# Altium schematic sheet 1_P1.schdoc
size 431 x 309 mm; Symbol: Sheet-Symbol_A4; Device: Sheet-Symbol_A4; Company: EasyEDA.com; Drawed: EasyEDA Pro; Reviewed: EasyEDA Pro; Version: V0.1; Page Size: A3; @Project Name: FortissKnob; @Page Count: 1; @Update Date: 2023-03-24; @Create Date: 2023-03-01; @Schematic Name: Schematic2; Part Number: JLCPCB-002; @Page No: 1; @Page Name: P1
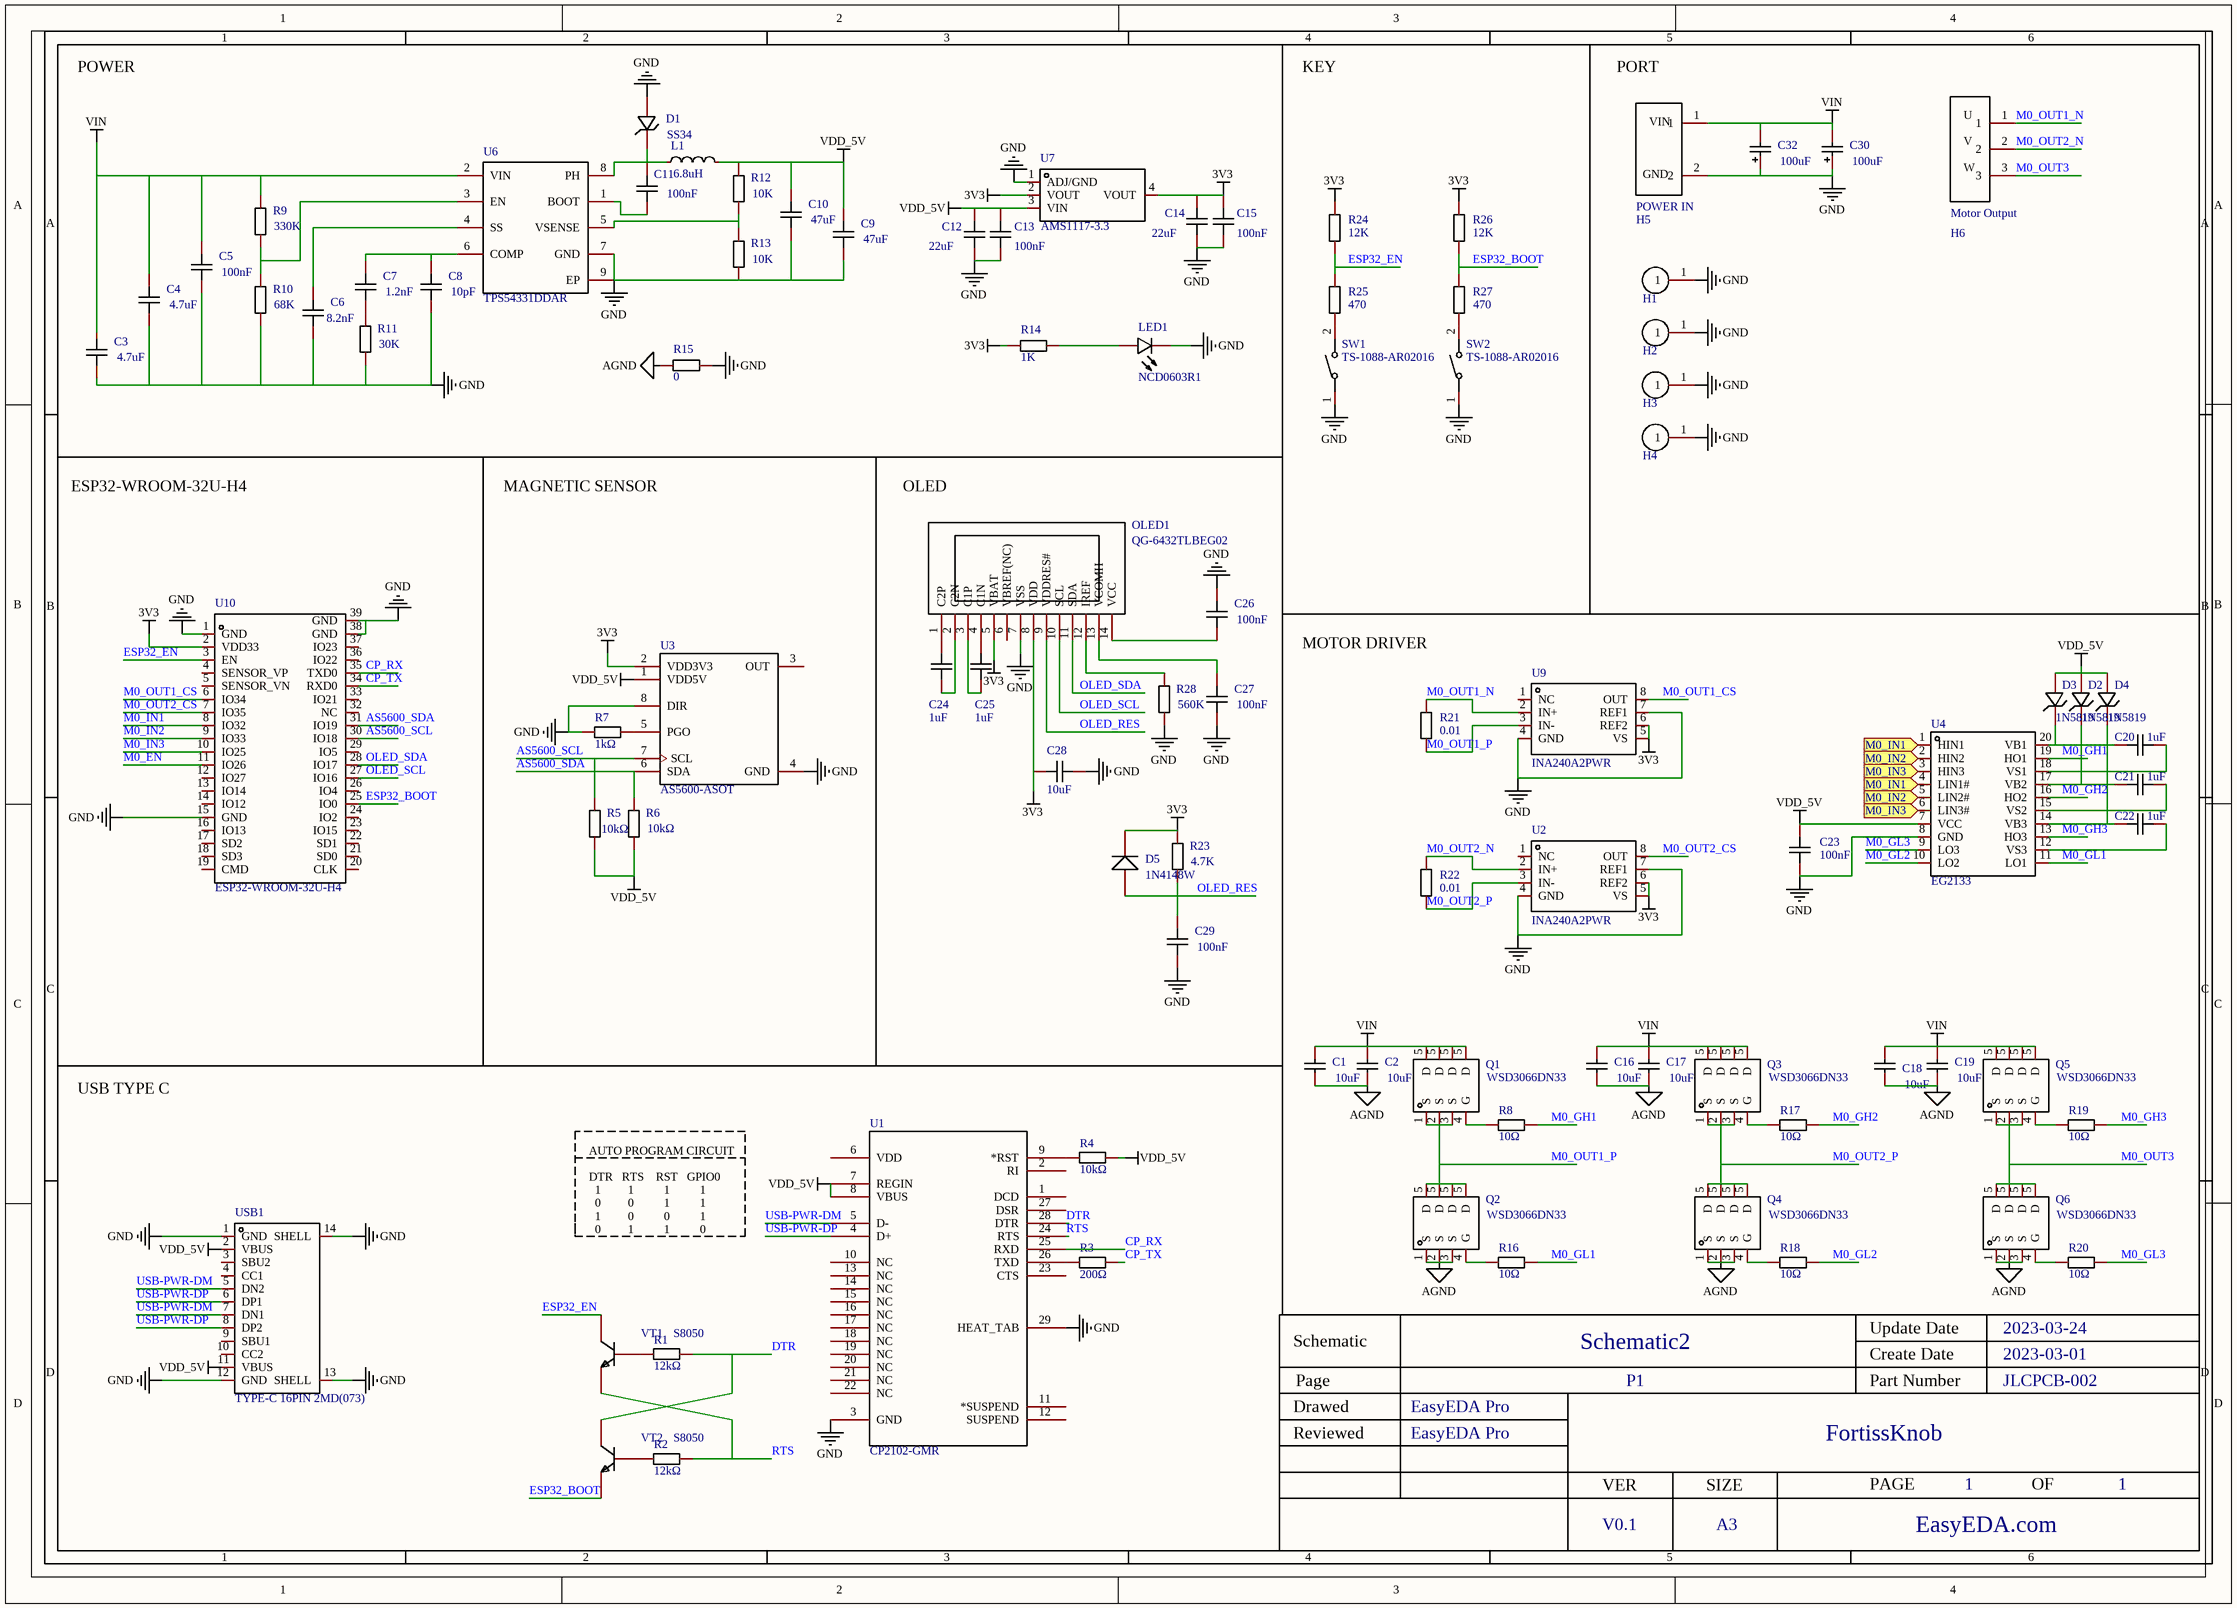
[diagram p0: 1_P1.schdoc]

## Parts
C1  10uF  [C0603]
C2  10uF  [C0603]
C3  4.7uF  [C0603]
C4  4.7uF  [C0603]
C5  100nF  [C0603]
C6  8.2nF  [C0603]
C7  1.2nF  [C0603]
C8  10pF  [C0603]
C9  47uF  [C0603]
C10  47uF  [C0603]
C11  100nF  [C0603]
C12  22uF  [C0603]
C13  100nF  [C0603]
C14  22uF  [C0603]
C15  100nF  [C0603]
C16  10uF  [C0603]
C17  10uF  [C0603]
C18  10uF  [C0603]
C19  10uF  [C0603]
C20  1uF  [C0603]
C21  1uF  [C0603]
C22  1uF  [C0603]
C23  100nF  [C0603]
C24  1uF  [C0603]
C25  1uF  [C0603]
C26  100nF  [C0603]
C27  100nF  [C0603]
C28  10uF  [C0603]
C29  100nF  [C0603]
C30  100uF  [CAP-SMD_L7.3-W4.3-R-RD]
C32  100uF  [CAP-SMD_L7.3-W4.3-R-RD]
D1  SS34  [SMA_L4.3-W2.7-LS5.1-RD]
D2  1N5819  [SMA_L4.4-W2.6-LS5.0-RD]
D3  1N5819  [SMA_L4.4-W2.6-LS5.0-RD]
D4  1N5819  [SMA_L4.4-W2.6-LS5.0-RD]
D5  1N4148W  [SOD-123_L2.6-W1.8-LS3.7-RD]
H1  M3定位孔  (value not drawn)
H2  M3定位孔  (value not drawn)
H3  M3定位孔  (value not drawn)
H4  M3定位孔  (value not drawn)
H5  POWER IN  [POWER IN]
H6  Motor Output  [Motor Output Pin]
L1  6.8uH  [L0603]
LED1  NCD0603R1  [LED0603-RD_RED]
OLED1  QG-6432TLBEG02  [OLED-SMD_QG-6432TLBEG02]
Q1  WSD3066DN33  [DFN-8_L3.3-W3.3-P0.65-BL]
Q2  WSD3066DN33  [DFN-8_L3.3-W3.3-P0.65-BL]
Q3  WSD3066DN33  [DFN-8_L3.3-W3.3-P0.65-BL]
Q4  WSD3066DN33  [DFN-8_L3.3-W3.3-P0.65-BL]
Q5  WSD3066DN33  [DFN-8_L3.3-W3.3-P0.65-BL]
Q6  WSD3066DN33  [DFN-8_L3.3-W3.3-P0.65-BL]
R1  12kΩ  [R0603]
R2  12kΩ  [R0603]
R3  200Ω  [R0603]
R4  10kΩ  [R0603]
R5  10kΩ  [R0603]
R6  10kΩ  [R0603]
R7  1kΩ  [R0603]
R8  10Ω  [R0603]
R9  330K  [R0603]
R10  68K  [R0603]
R11  30K  [R0603]
R12  10K  [R0603]
R13  10K  [R0603]
R14  1K  [R0603]
R15  0  [R0603]
R16  10Ω  [R0603]
R17  10Ω  [R0603]
R18  10Ω  [R0603]
R19  10Ω  [R0603]
R20  10Ω  [R0603]
R21  0.01  [R0603]
R22  0.01  [R0603]
R23  4.7K  [R0603]
R24  12K  [R0603]
R25  470  [R0603]
R26  12K  [R0603]
R27  470  [R0603]
R28  560K  [R0603]
SW1  TS-1088-AR02016  [SW-SMD_L3.9-W3.0-P4.45]
SW2  TS-1088-AR02016  [SW-SMD_L3.9-W3.0-P4.45]
U1  CP2102-GMR  [WQFN-28_L5.0-W5.0-P0.50-BL-EP3.2]
U2  INA240A2PWR  [TSSOP-8_L4.4-W3.0-P0.65-LS6.4-BL]
U3  AS5600-ASOT  [SOIC-8_L5.0-W4.0-P1.27-LS6.0-BL]
U4  EG2133  [TSSOP-20_L6.5-W4.4-P0.65-LS6.4-BL]
U6  TPS54331DDAR  [SOIC-8_L5.0-W4.0-P1.27-LS6.0-BL-EP2.0]
U7  AMS1117-3.3  [SOT-223_L6.5-W3.5-P2.30-LS7.0-BR]
U9  INA240A2PWR  [TSSOP-8_L4.4-W3.0-P0.65-LS6.4-BL]
U10  ESP32-WROOM-32U-H4  [WIFI-SMD_ESP32-WROOM-32UE-A]
USB1  TYPE-C 16PIN 2MD(073)  [USB-C-SMD_TYPE-C-6PIN-2MD-073]
VT1  S8050  [SOT-23_L2.9-W1.3-P1.90-LS2.4-BR]
VT2  S8050  [SOT-23_L2.9-W1.3-P1.90-LS2.4-BR]

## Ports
M0_IN1 (in), M0_IN2 (in), M0_IN3 (in)

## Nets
3V3: C14.1 C15.1 C28.2 D5.1(C) OLED1.5(VBAT) OLED1.8(VDD) R14.1 R23.2 R24.2 R26.2 U2.5(VS) U2.6(REF2) U3.2(VDD3V3) U7.2(VOUT) U7.4(VOUT) U9.5(VS) U9.6(REF2) U10.2(VDD33)
AGND: C1.1 C2.1 C16.1 C17.1 C18.1 C19.1 Q2.1(S) Q2.2(S) Q2.3(S) Q4.1(S) Q4.2(S) Q4.3(S) Q6.1(S) Q6.2(S) Q6.3(S) R15.1
GND: C3.2 C4.2 C5.2 C6.2 C8.2 C9.2 C10.2 C12.2 C13.2 C14.2 C15.2 C23.1 C26.2 C27.1 C28.1 C29.2 C30.1 C32.1 D1.2(A) H1.1 H2.1 H3.1 H4.1 H5.2 LED1.1(K) OLED1.7(VSS) R7.2 R10.1 R11.1 R13.1 R15.2 R28.1 SW1.1 SW2.1 U1.3(GND) U1.29(HEAT_TAB) U2.4(GND) U2.7(REF1) U3.4(GND) U3.8(DIR) U4.8(GND) U6.7(GND) U6.9(EP) U7.1(ADJ/GND) U9.4(GND) U9.7(REF1) U10.1(GND) U10.15(GND) U10.38(GND) U10.39(GND) USB1.1(GND) USB1.12(GND) USB1.13(SHELL) USB1.14(SHELL)
VDD_5V: C9.1 C10.1 C12.1 C13.1 C23.2 D2.2(A) D3.2(A) D4.2(A) L1.2 R4.1 R5.1 R6.1 R12.2 U1.7(REGIN) U1.8(VBUS) U3.1(VDD5V) U4.7(VCC) U7.3(VIN) USB1.2(VBUS) USB1.11(VBUS)
VIN: C1.2 C2.2 C3.1 C4.1 C5.1 C16.2 C17.2 C18.2 C19.2 C30.2 C32.2 H5.1 Q1.5(D) Q3.5(D) Q5.5(D) R9.2 U6.2(VIN)
AS5600_SCL: R5.2 U3.7(SCL) U10.30(IO18)
AS5600_SDA: R6.2 U3.6(SDA) U10.31(IO19)
CP_RX: U1.25(RXD) U10.35(TXD0)
CP_TX: R3.1 U10.34(RXD0)
DTR: R1.1 U1.28(DTR) VT2.3(C)
ESP32_BOOT: R26.1 R27.2 U10.25(IO0) VT2.2(E)
ESP32_EN: R24.1 R25.2 U10.3(EN) VT1.3(C)
M0_EN: U10.11(IO26)
M0_GH1: R8.2 U4.19(HO1)
M0_GH2: R17.2 U4.16(HO2)
M0_GH3: R19.2 U4.13(HO3)
M0_GL1: R16.2 U4.11(LO1)
M0_GL2: R18.2 U4.10(LO2)
M0_GL3: R20.2 U4.9(LO3)
M0_IN1: U4.1(HIN1) U4.4(LIN1#) ; port M0_IN1
M0_IN1: U10.8(IO32)  [a separate net that carries the same name]
M0_IN2: U4.2(HIN2) U4.5(LIN2#) ; port M0_IN2
M0_IN2: U10.9(IO33)  [a separate net that carries the same name]
M0_IN3: U4.3(HIN3) U4.6(LIN3#) ; port M0_IN3
M0_IN3: U10.10(IO25)  [a separate net that carries the same name]
M0_OUT1_CS: U9.8(OUT) U10.6(IO34)
M0_OUT1_N: H6.1 R21.1 U9.2(IN+)
M0_OUT1_P: Q1.1(S) Q1.2(S) Q1.3(S) Q2.5(D) R21.2 U9.3(IN-)
M0_OUT2_CS: U2.8(OUT) U10.7(IO35)
M0_OUT2_N: H6.2 R22.1 U2.2(IN+)
M0_OUT2_P: Q3.1(S) Q3.2(S) Q3.3(S) Q4.5(D) R22.2 U2.3(IN-)
M0_OUT3: H6.3 Q5.1(S) Q5.2(S) Q5.3(S) Q6.5(D)
OLED_RES: C29.1 D5.2(A) OLED1.9(VDDRES#) R23.1
OLED_SCL: OLED1.10(SCL) U10.27(IO16)
OLED_SDA: OLED1.11(SDA) U10.28(IO17)
RTS: R2.1 U1.24(RTS) VT1.2(E)
USB-PWR-DM: U1.5(D-) USB1.5(DN2) USB1.7(DN1)
USB-PWR-DP: U1.4(D+) USB1.6(DP1) USB1.8(DP2)
NetC6_1: C6.1 U6.4(SS)
NetC7_1: C7.1 C8.1 U6.6(COMP)
NetC7_2: C7.2 R11.2
NetC11_1: C11.1 D1.1(C) L1.1 U6.8(PH)
NetC11_2: C11.2 U6.1(BOOT)
NetC20_1: C20.1 D3.1(C) U4.20(VB1)
NetC20_2: C20.2 U4.18(VS1)
NetC21_1: C21.1 D2.1(C) U4.17(VB2)
NetC21_2: C21.2 U4.15(VS2)
NetC22_1: C22.1 D4.1(C) U4.14(VB3)
NetC22_2: C22.2 U4.12(VS3)
NetC24_1: C24.1 OLED1.1(C2P)
NetC24_2: C24.2 OLED1.2(C2N)
NetC25_1: C25.1 OLED1.4(C1N)
NetC25_2: C25.2 OLED1.3(C1P)
NetC26_1: C26.1 OLED1.14(VCC)
NetC27_2: C27.2 OLED1.13(VCOMH)
NetLED1_2: LED1.2(A) R14.2
NetOLED1_12: OLED1.12(IREF) R28.2
NetQ1_4: Q1.4(G) R8.1
NetQ2_4: Q2.4(G) R16.1
NetQ3_4: Q3.4(G) R17.1
NetQ4_4: Q4.4(G) R18.1
NetQ5_4: Q5.4(G) R19.1
NetQ6_4: Q6.4(G) R20.1
NetR1_2: R1.2 VT1.1(B)
NetR2_2: R2.2 VT2.1(B)
NetR3_2: R3.2 U1.26(TXD)
NetR4_2: R4.2 U1.9(*RST)
NetR7_1: R7.1 U3.5(PGO)
NetR9_1: R9.1 R10.2 U6.3(EN)
NetR12_1: R12.1 R13.2 U6.5(VSENSE)
NetR25_1: R25.1 SW1.2
NetR27_1: R27.1 SW2.2

Not connected (* = marked no-connect by the designer): OLED1 6(VBREF(NC)); U1 1(DCD) 2(RI) 6(VDD) 10(NC) 11(*SUSPEND) 12(SUSPEND) 13(NC) 14(NC) 15(NC) 16(NC) 17(NC) 18(NC) 19(NC) 20(NC) 21(NC) 22(NC) 23(CTS) 27(DSR); U2 1(NC); U3 3(OUT); U9 1(NC); U10 4(SENSOR_VP) 5(SENSOR_VN) 12(IO27) 13(IO14) 14(IO12) 16(IO13) 17(SD2) 18(SD3) 19(CMD) 20(CLK) 21(SD0) 22(SD1) 23(IO15) 24(IO2) 26(IO4) 29(IO5) 32(NC) 33(IO21) 36(IO22) 37(IO23); USB1 3(SBU2) 4(CC1) 9(SBU1) 10(CC2)

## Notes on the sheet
- POWER
- KEY
- PORT
- ESP32-WROOM-32U-H4
- MAGNETIC SENSOR
- OLED
- MOTOR DRIVER
- USB TYPE C
- AUTO PROGRAM CIRCUIT
  DTR   RTS    RST   GPIO0
  1         1          1          1
  0         0          1          1
  1         0          0          1
  0         1          1          0

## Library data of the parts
C1 C2 C16-C19 = 0603B104K500NT_C30926: Capacitance: Tolerance:±10% Tolerance:±10% Voltage Rated: Temperature Coefficient:; Manufacturer: FH(风华); Add into BOM: yes; Tolerance: ±10%
C3-C15 C20-C29 = CAP_0603: Symbol: CAP; Convert to PCB: yes
C30 C32 = TAJE107M025RNJ: Capacitance: Tolerance:±20% Tolerance:±20% Rated Voltage: Equivalent Series Resistance(ESR):300mΩ@100kHz Operating Temperature:-55℃~+125℃ Operating Temperature:-55℃~+125℃; Manufacturer: Kyocera AVX; Add into BOM: yes; Tolerance: ±20%
D1 = SS34_C3014011: Reverse Voltage (Vr):40V Average Rectified Current (Io):3A Forward Voltage (Vf@If):550mV@3A Reverse Leakage Current (Ir):100uA@40V; Manufacturer: FOSAN(富信); Add into BOM: yes; Reverse Voltage (Vr): 40V; Average Rectified Current (Io): 3A
D2-D4 = 1N5819_C437199: Reverse Voltage (Vr):40V Average Rectified Current (Io):1A Forward Voltage (Vf@If):500mV@1A; Manufacturer: KEXIN(科信); Add into BOM: yes; Reverse Voltage (Vr): 40V; Average Rectified Current (Io): 1A
D5 = 1N4148W_C129869: Diode Configuration: Power Dissipation: Reverse Voltage (Vr): Average Rectified Current (Io): Forward Voltage (Vf@If):1V@10mA Reverse Leakage Current:5uA@75V Reverse Recovery Time (trr): Operating Temperature:-65℃~+150℃@(Tj) Operating Temperature:-65℃~+15; Manufacturer: 迪一; Symbol: 1N4148W-C129869; Add into BOM: yes
H1-H4 = M3定位孔: Add into BOM: yes
H5 = Power Hole: Add into BOM: yes
H6 = Motor Output Hole: Add into BOM: yes
L1 = L_0603: Symbol: 电感; Add into BOM: yes
LED1 = NCD0603R1_C84263: Emitted Color:红灯; Manufacturer: 国星光电; Symbol: FC-DA1608HRK-620D; Add into BOM: yes; Emitted Color: 红灯
OLED1 = QG-6432TLBEG02: Size:0.49 Screen Resolution:- Master Control Chip:- Supply Voltage:- Working Current:- Colour:-; Manufacturer: Allvision(全智景); Add into BOM: yes
Q1-Q6 = WSD3066DN33: Type: Drain Source Voltage (Vdss): Continuous Drain Current (Id): Power Dissipation (Pd): Drain Source On Resistance (RDS(on)@Vgs,Id):5.7mΩ@10V,35A Gate Threshold Voltage (Vgs(th)@Id):2.5V@250uA; Manufacturer: WINSOK(微硕); Add into BOM: yes
R1-R8 R16-R20 = 0603WAF1002T5E: Type:Thick Film Resistors Resistance: Tolerance:±1% Tolerance:±1% Power(Watts): Temperature Coefficient:±100ppm/℃ Temperature Coefficient:±100ppm/℃ Overload Voltage (Max): Operating Temperature Range:-55℃~+155℃ Operating Temperature Range:-55℃~+155℃; Manufacturer: UNI-ROYAL(厚声); Add into BOM: yes; Tolerance: ±1%
R9-R15 R21-R28 = Res_0603: Symbol: Res; Convert to PCB: yes
SW1 SW2 = TS-1088-AR02016: Contact Current:50mA Voltage Rating (DC):12V Insulation Resistance:100MΩ Circuit:SPST Mounting Style:Brick nogging Actuator Style:Round Button Actuator/Cap Color:Black Operating Force:160gf@±50gf Mechanical Life:100000 Operating Temperature:-30℃~+80℃ Oper; Manufacturer: XUNPU(讯普); Add into BOM: yes; Contact Current: 50mA; Voltage Rating (DC): 12V; Insulation Resistance: 100MΩ; Circuit: SPST; Actuator/Cap Color: Black; Mechanical Life: 100000; Pin Style: SMDSplicing; Switch Length: 4mm; Switch Width: 3mm; Switch Height: 2mm; Strike Gundam: NO
U1 = CP2102-GMR: Type: Protocol: Number of Drivers/Receivers: Data Rate: Supply Voltage:; Manufacturer: SILICON LABS(芯科); PART DESC: SINGLE-CHIP USB TO UART BRIDGE, QFN28, RoHS.; PART NUMBER: CP2102; Add into BOM: yes; Origin Footprint: QFN-28; MFG #1: SILICON LABS
U2 U9 = INA240A2PWR: Manufacturer: TI(德州仪器); Add into BOM: yes
U3 = AS5600-ASOT: SENSOR ANGLE 360DEG SMD; Manufacturer: ams(艾迈斯半导体); Add into BOM: yes; Origin Footprint 1: FP-AS5600-ASOM-IPC_C; Sensing Method: Hall Effect; Origin Footprint 2: FP-AS5600-ASOM-IPC_B; Origin Footprint 3: FP-AS5600-ASOM-IPC_A
U4 = EG2133_C190343: Manufacturer: EG(屹晶微); Add into BOM: yes
U6 = TPS54331DDAR: Function:Step-down type Synchronous Rectification:- Number of Outputs:- Topology:- Input Voltage:- Input Voltage:- Output Current (Max):- Switching Frequency:-; Manufacturer: TI(德州仪器); Add into BOM: yes
U7 = AMS1117-3.3_C351785: Manufacturer: PUOLOP(迪浦); Add into BOM: yes
U10 = ESP32-WROOM-32U-H4: Manufacturer: ESPRESSIF(乐鑫); Add into BOM: yes
USB1 = TYPE-C 16PIN 2MD(073): Connector Type:Type-C Standard:- Gender:Female Number of Contacts:16 Number of Ports:1 Mounting Style:Surface Mount Current Rating - Power (Max):5A Operating Temperature Range:-25℃~+85℃ Operating Temperature Range:-25℃~+85℃; Manufacturer: SHOU HAN(首韩); Add into BOM: yes; Gender: Female; Number of Contacts: 16; Number of Ports: 1; Current Rating - Power (Max): 5A
VT1 VT2 = S8050_C397180: Transistor Type: Collector-Emitter Breakdown Voltage (Vceo): Collector Current (Ic): Power Dissipation (Pd): Collector Cut-Off Current (Icbo):150nA Collector-Emitter Saturation Voltage (VCE(sat)@Ic,Ib):500mV@800mA,80mA DC Current Gain (hFE@Ic,Vce):200@100; Manufacturer: AnBon(安邦); Add into BOM: yes; Collector Cut-Off Current (Icbo): 150nA; DC Current Gain (hFE@Ic,Vce): 200@100mA,1V; Origin Footprint: SMT_TRIODE_NPN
